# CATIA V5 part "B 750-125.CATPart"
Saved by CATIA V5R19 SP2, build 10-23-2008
Part number: B 750-125
Bounding box of the stored display mesh (mm): x -22.494 to 22.494, y -22.494 to 22.494, z 0 to 335
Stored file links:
  C:\Users\Bora\Desktop\3D Katı model\B serisi\B 750\B 750-125.CATPart
  C:\Program Files\Dassault Systemes\B19\intel_a\reffiles\standard\MetricThickPitch.txt
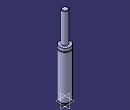
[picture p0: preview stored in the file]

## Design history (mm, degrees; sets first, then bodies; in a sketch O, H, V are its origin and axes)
Body1 (main body)
  Sketch1 on yz-plane, origin (0, 0, 0), H (0, 1, 0), V (0, 0, 1)
    point P3 (12, 334)
    point P5 (12, 334)
    point P7 (22.5, 194.5)
    point P8 (22.5, 192.5)
    point P12 (22.5, 192.5)
    point P13 (22.5, 194.5)
    line L1 (22.5, 0) -> (22.5, 4)
    line L2 (12, 334) -> (12, 208)
    arc A1 centre (11, 334) radius 1 from (12, 334) to (11, 335) ccw
    arc A2 centre (22.5, 193.5) radius 1 from (22.5, 194.5) to (22.5, 192.5) ccw
    line L3 (20, 7.5) -> (20, 4)
    line L4 (22.5, 7.5) -> (22.5, 192.5)
    line L5 (22.5, 194.5) -> (22.5, 208)
    line L6 (11, 335) -> (0, 335)
    point P15 (0, 335)
    line L7 (12, 208) -> (22.5, 208)
    line L8 (0, 0) -> (22.5, 0)
    line L9 (20, 7.5) -> (22.5, 7.5)
    line L10 (20, 4) -> (22.5, 4)
    coincidence: P15 V, P3 P5, P7 P13, P8 P12
    tangency: L6 A1
    horizontal: L7 H, L8 H, L9 H, L10 H
  Shaft1: profile Sketch1, axis Sketch1.V, angle 360
  Sketch2 on face of Shaft1 from Sketch1.L8, origin (0, 0, 0), H (1, 0, 0), V (0, -1, 0)
    point P1 (10, 0)
    distance P1 V = 10
  Hole1: placed by Sketch2, at (10, 0, 0) direction (0, 0, 1), diameter 6.647, depth 13, threaded "M8", thread diameter 8, thread depth 13, pitch 1.25
  CircPattern1: of Hole1, instances 2, angular step 180, axis from xy-plane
